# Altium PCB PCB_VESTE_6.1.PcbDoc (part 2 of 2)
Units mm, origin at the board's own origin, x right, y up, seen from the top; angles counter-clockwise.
Board outline 60.48 x 91 mm, 4 copper layers (Top Copper (GND), Signal Layer 1 (PWR), Signal Layer 2 (GND), Bottom Copper(SIG)), stack 0.97 mm thick; 103 components, 68 nets, 385 pads, 720 vias.
Unrouted connection lines stored in the file: 5.
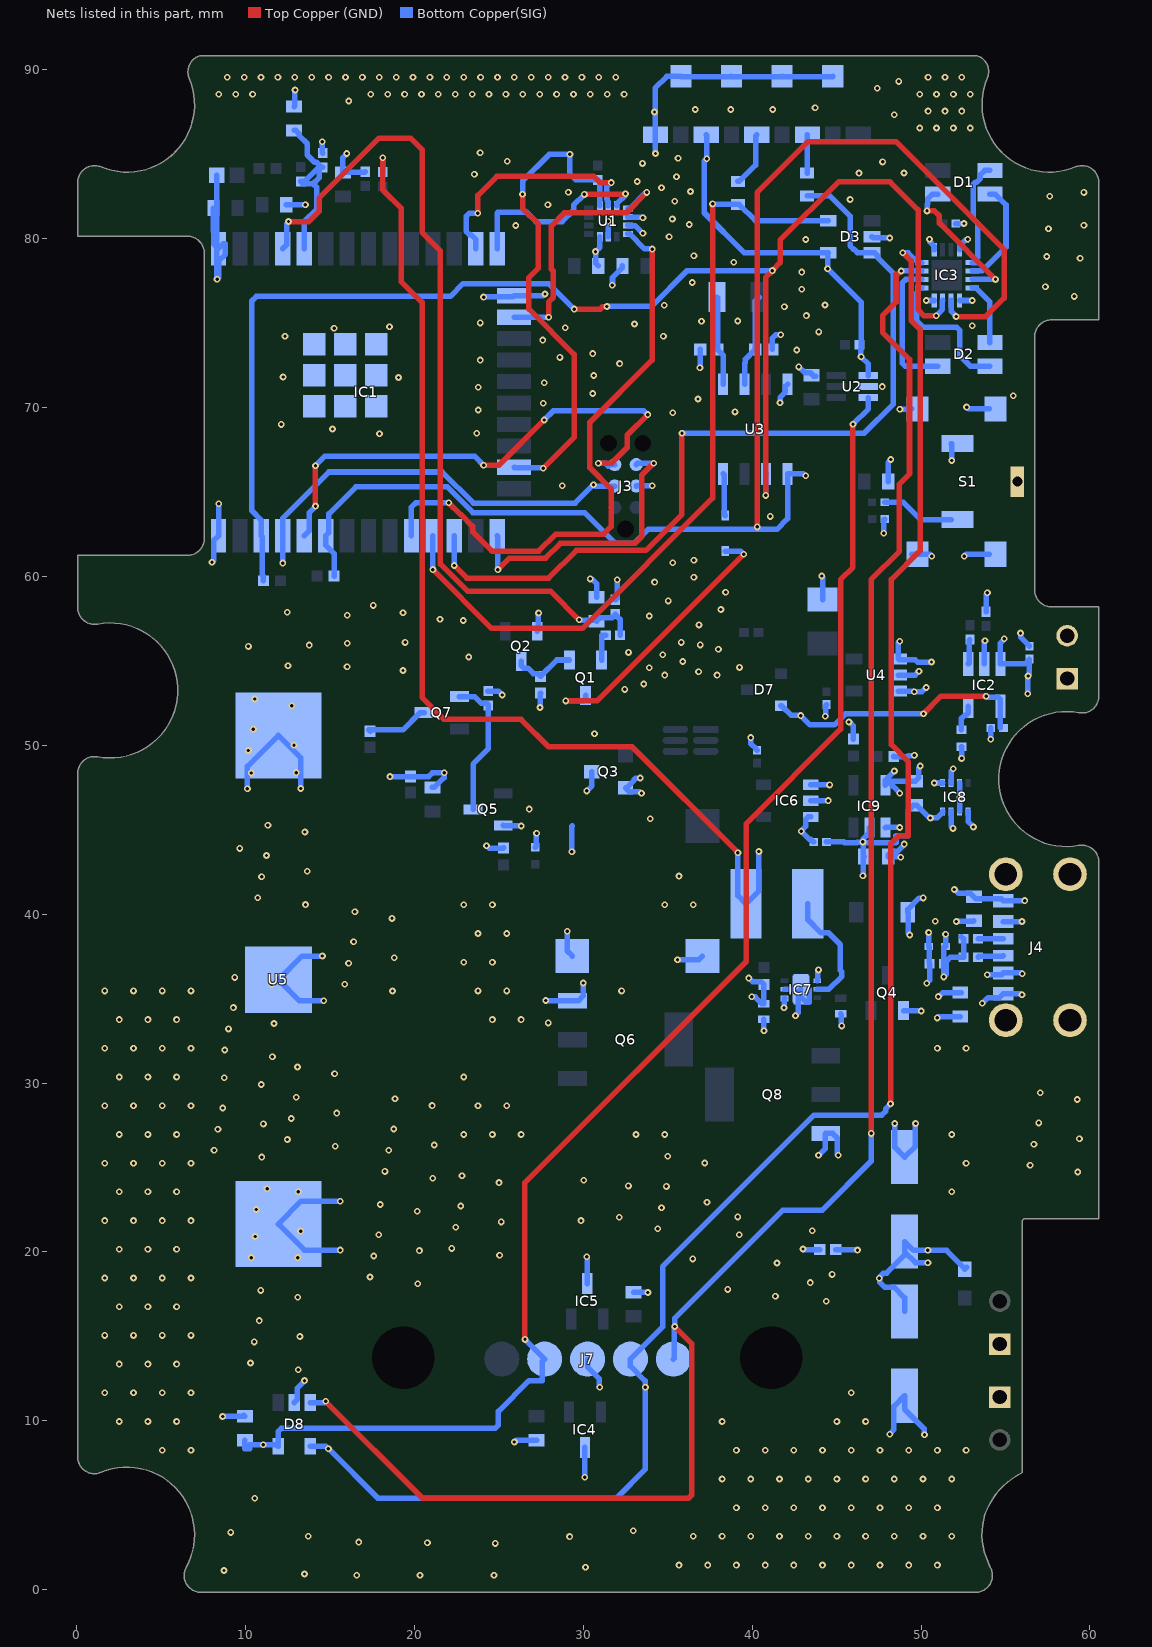
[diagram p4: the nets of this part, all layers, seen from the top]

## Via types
v1: diameter 0.4, hole 0.2, Top Copper (GND) to Bottom Copper(SIG), 720 vias

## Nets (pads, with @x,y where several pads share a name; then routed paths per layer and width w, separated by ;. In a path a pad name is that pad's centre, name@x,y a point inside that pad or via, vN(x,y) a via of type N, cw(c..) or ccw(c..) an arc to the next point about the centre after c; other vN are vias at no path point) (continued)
GND: C1.2 C2.2 C3.2 C4.2 C5.2 C6.2 C7.2 C8.2 C9.2 C10.2 C11.2 C12.2 C13.2 C14.2 C15.1 C16.1 C17.2 C18.2 C19.2 C20.2 C21.2 C22.2 C23.2 C24.2 C25.1 C26.2 C27.2 C28.2 C29.2 C30.2 C31.1 C32.2 D3.2 D8.2 IC1.1 IC1.15 IC1.38 IC1.39 IC1.40 IC1.41 IC1.42 IC1.43 IC1.44 IC1.45 IC1.46 IC1.47 IC2.2 IC3.1 IC3.4 IC3.9 IC3.12 IC4.3 IC5.3 IC6.2 IC7.2 IC7.4 IC7.7 IC7.8 IC7.9 IC8.1 IC8.4 IC8.5 IC9.2 J2.2 J3.4 J4.A12 J4.B12 J4.MH1 J4.MH2 J4.MH3 J4.MH4 J7.3 MP1.1 MP2.1 pad.2@51.444,38.09 pad.9 pad.10 pad.11 pad.12 pad.13 Q2.2 Q3.2 Q5.2 Q6.3 Q8.3 R8.1 R9.2 R14.2 R15.1 R17.1 R19.1 R20.1 R21.1 R22.1 R27.2 R28.1 R29.2 R31.2 S1.MP1 S1.MP2 S1.MP3 S1.MP4 S1.MP5 U1.2 U1.3 U1.6 U1.7 U2.2 U3.4 U4.2 U5.3 | length 159.3
  Bottom Copper(SIG) w0.326: v1(8.008,60.837) 8.008,60.857 8.103,60.952 8.103,62.117 IC1.38@8.39,62.404 8.399,62.413 8.399,64.299 v1(8.408,64.307) ; C2.2@8.098,81.813 8.098,80.432 8.103,80.427 8.103,79.691 IC1.1@8.39,79.404 8.677,79.691 8.808,79.691 8.808,79.074 8.404,78.67 8.404,77.703 8.31,77.61 v1(8.31,77.59) 8.289,77.611 C3.2@8.289,83.762 ; v1(8.638,10.254) 8.64,10.256 9.82,10.256 9.883,10.319 C24.2@9.959,10.259 ; C1.2@12.415,82.004 v1(13.542,82.004) ; C6.2@12.867,87.825 12.916,87.873 12.916,88.786 v1(12.93,88.8) ; D8.2@12.879,11.079 13.061,11.261 13.061,11.936 13.485,12.36 v1(13.485,12.38) ; v1(14.537,85.737) 14.552,85.723 14.552,85.092 R8.1@14.576,85.068 ; v1(14.547,37.519) 13.344,37.519 U5.3@11.941,36.116 13.19,34.866 v1(14.627,34.866) ; v1(15.992,85.043) 15.992,85.023 15.765,84.796 C10.2@15.765,83.919 15.786,83.94 17.059,83.94 R17.1@17.08,83.962 ; v1(18.55,48.144) R27.2@19.766,48.144 20.837,48.144 21.064,48.37 v1(21.765,48.37) 21.751,48.356 21.751,48.086 21.165,47.5 C20.2@21.06,47.5 ; v1(24.092,76.539) 24.106,76.553 25.834,76.553 IC1.15@25.9,76.619 27.603,76.619 27.709,76.724 v1(27.728,76.724) ; v1(24.267,44.051) 24.287,44.051 24.425,43.913 25.267,43.913 R28.1@25.277,43.923 ; Q5.2@25.267,45.252 25.286,45.233 26.309,45.233 v1(26.323,45.219) ; v1(25.916,8.745) 25.936,8.745 26.023,8.832 27.224,8.832 C21.2@27.231,8.839 ; C22.2@27.154,43.949 27.215,44.01 27.215,44.772 v1(27.229,44.786) ; Q2.2@27.273,56.762 27.336,56.824 27.336,57.815 v1(27.35,57.83) ; v1(27.768,34.886) 27.778,34.876 29.343,34.876 Q6.3@29.353,34.866 29.7,34.866 29.987,35.153 v1(29.987,35.924) ; v1(30.079,6.655) 30.086,6.663 30.086,8.416 IC4.3@30.094,8.424 ; v1(30.203,19.707) 30.203,19.687 30.231,19.658 IC5.3@30.231,18.126 ; J7.3@30.25,13.65 30.25,13.175 30.95,12.475 30.95,11.994 v1(30.964,11.98) ; v1(30.414,59.851) 30.428,59.837 30.52,59.837 30.787,59.57 C9.2@30.787,58.766 ; C4.2@30.89,78.39 30.732,78.548 30.732,79.217 v1(30.718,79.231) 30.975,79.489 U1.7@30.975,80.119 ; U1.6@31.475,80.119 v1(31.475,81.031) ; v1(31.712,77.237) 31.726,77.251 31.726,77.696 32.315,78.285 C5.2@32.315,78.39 ; R15.1@31.89,58.614 31.993,58.717 31.993,59.784 v1(32.007,59.798) ; U1.3@32.638,80.781 32.65,80.769 33.057,80.769 33.505,80.321 v1(33.525,80.321) ; U1.2@32.638,81.281 33.456,81.281 33.505,81.233 v1(33.525,81.233) ; C23.2@32.977,17.607 32.984,17.599 33.816,17.599 v1(33.823,17.592) ; J3.4@33.134,65.351 33.138,65.356 34.072,65.356 v1(34.076,65.36) ; v1(33.376,48.064) 33.372,48.06 33.105,48.06 33.02,47.975 33.02,47.945 32.553,47.478 Q3.2@32.503,47.478 32.74,47.241 33.343,47.241 33.422,47.161 v1(33.442,47.161) ; v1(34.21,87.5) 34.21,87.48 34.271,87.419 pad.9@34.271,86.151 ; v1(34.271,85.043) 34.257,85.057 34.257,85.608 34.25,85.614 34.25,88.911 34.95,89.611 pad.13@35.771,89.611 35.771,89.586 pad.12@38.771,89.586 ; v1(36.9,72.361) 36.9,72.381 36.925,72.406 C15.1@36.925,73.44 ; pad.12@38.771,89.611 pad.12@38.771,89.586 ; v1(39.789,36.212) 39.809,36.212 40.022,35.999 40.525,35.999 R29.2@40.687,35.837 C30.2@40.687,34.689 40.575,34.689 40.166,35.098 39.99,35.098 v1(39.976,35.112) ; v1(39.909,50.453) 39.924,50.439 39.924,50.088 40.211,49.8 40.211,49.779 C28.2@40.284,49.705 ; C16.1@41.195,73.44 41.195,74.104 41.392,74.3 41.671,74.3 v1(41.685,74.314) ; v1(41.642,70.276) 41.656,70.29 41.656,70.593 41.953,70.89 41.953,71.24 U3.4@42.09,71.377 ; pad.11@41.771,89.611 pad.11@41.771,89.586 ; IC7.2@41.912,35.555 IC7.8@42.412,35.555 ; IC7.8@42.418,35.555 42.418,35.56 IC7.7@42.728,35.25 ; v1(42.559,33.977) 42.559,33.997 42.728,34.166 IC7.7@42.728,35.25 ; v1(42.749,72.406) 42.769,72.406 43.117,72.059 43.442,72.059 43.644,71.857 C14.2@43.749,71.857 ; IC7.7@42.887,35.555 42.728,35.396 IC7.7@42.728,35.25 ; IC7.9@43.362,35.555 43.362,34.773 43.205,34.773 IC7.7@42.728,35.25 ; IC6.2@43.462,46.711 43.47,46.718 44.494,46.718 v1(44.501,46.725) ; IC7.4@43.862,36.055 43.866,36.093 43.866,36.621 43.924,36.679 v1(43.924,36.699) ; v1(43.926,25.716) 44.312,26.102 44.312,26.967 Q8.3@44.361,27.016 44.761,27.016 45.048,26.729 45.048,25.782 45.095,25.736 v1(45.095,25.716) ; v1(44.119,60.024) 44.119,60.004 44.162,59.961 C25.1@44.162,58.63 ; v1(44.331,51.718) 44.345,51.732 44.345,52.342 C26.2@44.412,52.409 ; C27.2@44.393,44.277 45.41,44.277 45.466,44.221 46.183,44.221 46.225,44.263 46.542,44.263 v1(46.556,44.277) ; pad.10@44.771,89.611 44.771,89.586 pad.11@41.771,89.586 ; C29.2@45.242,34.093 45.283,34.052 45.283,33.395 v1(45.297,33.381) ; v1(45.726,51.376) 45.74,51.362 45.778,51.362 45.989,51.151 R31.2@45.989,50.361 ; v1(46.556,42.266) 46.57,42.28 46.57,43.351 C31.1@46.629,43.41 46.584,43.455 46.584,44.263 46.57,44.277 46.584,44.291 46.584,44.472 46.939,44.827 IC9.2@46.939,45.127 ; v1@46.584,44.221 48.514,44.221 48.514,44.628 48.87,44.628 48.895,44.653 49.251,44.653 49.251,46.149 49.545,46.444 49.756,46.444 50.496,45.704 50.535,45.704 v1(50.549,45.69) 50.564,45.704 50.954,45.704 51.278,46.028 IC8.4@51.278,46.089 ; D3.2@47.092,80.119 47.169,80.042 v1(48.146,80.042) ; v1(47.789,62.548) 47.803,62.562 47.803,63.34 R19.1@47.859,63.397 ; C11.2@48.05,65.614 48.05,66.744 48.207,66.901 v1(48.207,66.921) ; v1(48.146,9.203) 48.146,9.223 48.392,9.469 48.392,10.845 C18.2@49.029,11.482 49.029,10.682 50.186,9.524 50.186,9.188 v1(50.2,9.174) ; v1(48.439,27.6) 48.439,26.203 C19.2@49.029,25.614 49.666,26.251 49.666,27.59 v1(49.676,27.6) ; U4.2@48.655,54.156 49.644,54.156 49.871,54.383 v1(49.879,54.383) ; v1(48.745,69.902) 49.426,69.902 S1.MP2@49.439,69.914 ; S1.MP3@49.439,61.314 50.513,61.314 v1(50.629,61.198) ; v1(50.308,76.337) IC3.12@50.777,76.337 ; v1(50.499,79.962) 50.513,79.948 50.513,79.826 50.777,79.561 IC3.1@50.777,79.337 ; v1(50.777,47.765) IC8.5@51.278,47.765 ; v1(50.952,33.855) 50.972,33.855 51.052,33.935 C17.2@52.317,33.935 ; v1(51.337,36.283) v1@51.345,36.291 ; v1(51.453,38.815) 51.448,38.811 51.448,38.094 pad.2@51.444,38.09 51.399,38.09 51.352,38.043 R22.1@51.352,37.069 51.345,37.061 v1@51.345,36.291 ; v1(51.972,41.456) 51.992,41.456 52.223,41.225 52.921,41.225 C13.2@53.123,41.023 53.24,40.906 54.751,40.906 J4.B12@54.867,40.79 56.125,40.79 v1(56.139,40.803) ; C12.2@52.058,80.894 v1(52.537,80.894) ; IC3.9@52.277,76.337 v1(53.027,76.337) ; IC3.4@52.277,79.337 52.277,79.561 52.664,79.948 52.75,79.948 v1(52.764,79.962) ; R20.1@52.383,38.652 52.495,38.54 R20.1@52.52,38.54 R21.1@52.52,37.452 51.736,37.452 51.489,37.206 51.489,36.436 v1@51.345,36.291 ; R14.2@52.39,49.911 52.393,49.908 52.393,49.226 v1(52.397,49.223) ; v1(52.551,61.198) 52.667,61.314 S1.MP4@54.039,61.314 ; v1(52.695,70.027) 52.808,69.914 S1.MP1@54.039,69.914 ; IC8.1@52.777,46.089 52.791,46.076 52.791,45.484 53.096,45.178 v1(53.096,45.158) ; v1(53.621,34.727) 53.641,34.727 53.968,35.053 54.63,35.053 J4.A12@54.867,35.29 55.899,35.29 55.958,35.232 v1(55.978,35.232) ; IC2.2@53.743,54.813 53.743,56.13 53.787,56.174 v1(53.787,56.194) ; R9.2@53.845,57.905 53.845,58.93 53.925,59.01 v1(53.925,59.03) ; C7.2@54.121,51.036 54.121,50.784 54.113,50.792 54.113,50.375 v1(54.127,50.361) ; v1(55.885,56.644) 55.899,56.63 55.899,56.403 56.417,55.886 C8.2@56.417,55.864 ; pad.12@38.771,89.586 pad.11@41.771,89.586
  other v1: 16.587,0.849 20.327,0.849 24.708,0.849 13.485,0.929 8.717,1.13 30.126,1.319 35.664,1.454 37.364,1.454 39.064,1.454 40.764,1.454 42.464,1.454 44.164,1.454 45.864,1.454 47.564,1.454 49.264,1.454 50.964,1.454 24.779,2.735 20.767,2.771 16.694,2.815 13.711,3.154 29.186,3.14 36.514,3.154 38.214,3.154 39.914,3.154 41.614,3.154 43.314,3.154 45.014,3.154 46.714,3.154 48.414,3.154 50.114,3.154 51.814,3.154 9.117,3.387 32.953,3.493 39.064,4.854 40.764,4.854 42.464,4.854 44.164,4.854 45.864,4.854 47.564,4.854 49.264,4.854 50.964,4.854 10.539,5.41 38.214,6.554 39.914,6.554 41.614,6.554 43.314,6.554 45.014,6.554 46.714,6.554 48.414,6.554 50.114,6.554 51.814,6.554 5.064,8.254 6.764,8.254 39.064,8.254 40.764,8.254 42.464,8.254 44.164,8.254 45.864,8.254 47.564,8.254 49.264,8.254 50.964,8.254 52.664,8.254 2.514,9.954 4.214,9.954 5.914,9.954 38.214,9.954 45.014,9.954 46.714,9.954 1.664,11.654 3.364,11.654 5.064,11.654 6.764,11.654 45.864,11.654 13.119,13.023 2.514,13.354 4.214,13.354 5.914,13.354 10.291,13.423 10.517,14.67 13.214,14.99 1.664,15.054 3.364,15.054 5.064,15.054 6.764,15.054 10.811,15.931 2.514,16.754 4.214,16.754 5.914,16.754 44.39,17.07 13.083,17.319 41.372,17.376 10.89,17.719 38.544,17.776 20.197,18.111 43.439,18.182 1.664,18.454 3.364,18.454 5.064,18.454 6.764,18.454 17.369,18.511 44.729,18.666 41.467,19.343 36.478,19.583 17.595,19.757 25.041,19.808 20.292,20.077 2.514,20.154 4.214,20.154 5.914,20.154 22.213,20.208 17.889,21.018 39.233,21.018 43.557,21.245 34.4,21.37 22.439,21.454 25.136,21.775 1.664,21.854 3.364,21.854 5.064,21.854 6.764,21.854 29.864,21.854 32.126,22.054 39.144,22.073 20.162,22.407 34.626,22.616 22.733,22.715 17.969,22.807 37.323,22.937 2.514,23.554 4.214,23.554 5.914,23.554 51.814,23.554 34.92,23.877 32.668,23.906 25.006,24.104 30.028,24.246 21.077,24.366 22.812,24.504 59.281,24.729 18.249,24.766 56.453,25.129 1.664,25.254 3.364,25.254 5.064,25.254 6.764,25.254 52.664,25.254 37.192,25.266 10.96,25.612 34.999,25.666 8.132,26.012 18.475,26.012 15.304,26.253 21.172,26.333 56.679,26.375 12.476,26.653 59.376,26.696 2.514,26.954 4.214,26.954 5.914,26.954 22.914,26.954 24.614,26.954 26.314,26.954 33.114,26.954 34.814,26.954 51.814,26.954 8.358,27.259 18.768,27.273 11.055,27.579 56.972,27.636 12.702,27.899 15.399,28.22 8.652,28.52 1.664,28.654 3.364,28.654 5.064,28.654 6.764,28.654 21.041,28.662 23.764,28.654 25.464,28.654 59.245,29.025 18.848,29.062 12.996,29.16 57.052,29.425 10.925,29.908 8.732,30.308 2.514,30.354 4.214,30.354 5.914,30.354 22.914,30.354 15.269,30.549 13.075,30.949 11.587,31.558 8.759,31.958 1.664,32.054 3.364,32.054 5.064,32.054 6.764,32.054 50.964,32.054 52.664,32.054 8.985,33.205 11.682,33.525 27.919,33.561 2.514,33.754 4.214,33.754 5.914,33.754 24.614,33.754 26.314,33.754 9.279,34.466 1.664,35.454 3.364,35.454 5.064,35.454 6.764,35.454 18.701,35.451 23.764,35.454 25.464,35.454 32.264,35.454 15.873,35.851 11.552,35.855 9.358,36.255 16.099,37.098 22.914,37.154 24.614,37.154 18.796,37.418 16.393,38.359 23.764,38.854 25.464,38.854 50.842,39.576 18.666,39.748 16.473,40.148 13.548,40.566 22.914,40.554 24.614,40.554 34.814,40.554 36.514,40.554 10.72,40.966 10.946,42.213 35.664,42.254 13.643,42.533 11.24,43.474 9.66,43.891 13.513,44.862 11.32,45.262 33.964,45.654 26.791,46.219 30.662,50.689 32.447,53.308 33.582,53.63 34.814,54.154 37.92,54.156 36.822,54.352 19.319,54.43 33.902,54.588 39.248,54.611 16.01,54.649 12.514,54.712 35.892,54.962 23.215,55.23 34.708,55.362 32.676,55.499 37.996,55.681 10.164,55.854 13.767,55.93 36.925,55.942 16.018,56.039 19.446,56.09 35.804,56.09 36.846,57.128 22.885,57.386 21.509,57.465 33.902,57.656 16.018,57.703 19.319,57.849 12.46,57.882 38.147,58.042 17.56,58.282 35.024,58.549 38.423,59.054 34.218,59.664 36.547,59.947 35.298,60.804 36.547,60.949 41.062,63.551 28.745,65.36 17.927,68.447 23.694,68.478 15.145,68.727 12.114,68.999 35.29,69.685 38.983,69.741 23.773,69.85 27.629,70.25 36.79,70.502 55.453,70.702 30.551,70.827 23.773,71.201 47.698,71.24 27.689,71.467 19.051,71.774 12.219,71.804 30.623,71.895 32.146,72.602 23.892,72.809 28.614,72.966 30.551,73.193 42.632,73.404 27.592,73.993 12.335,74.226 34.74,74.226 43.941,74.477 15.24,74.697 28.932,74.724 18.519,74.777 53.027,74.843 33.025,74.949 23.892,75.01 36.998,75.103 39.148,75.12 43.207,75.442 41.904,75.974 34.793,76.053 44.309,76.072 59.076,76.579 42.936,76.998 57.362,77.157 36.447,77.401 42.936,78.02 38.904,78.597 59.415,78.837 57.439,78.942 36.547,78.983 43.165,79.948 35.079,80.119 57.542,80.587 26.003,80.781 59.642,80.798 36.265,80.837 35.275,81.163 27.9,82.004 35.415,82.209 45.797,82.318 57.622,82.511 59.642,82.738 29.115,82.752 36.344,82.794 34.628,83.02 33.199,83.385 35.517,83.659 23.55,83.815 46.32,83.883 48.985,83.886 33.504,84.457 47.72,84.545 25.494,84.58 35.611,84.763 23.886,85.088 49.915,86.554 50.915,86.554 51.915,86.554 52.915,86.554 48.411,87.34 50.415,87.554 51.415,87.554 52.415,87.554 36.632,87.646 38.727,87.646 41.21,87.646 43.724,87.758 16.114,88.154 8.414,88.554 9.414,88.554 10.414,88.554 17.414,88.554 18.414,88.554 19.415,88.554 20.415,88.554 21.415,88.554 22.415,88.554 23.415,88.554 24.415,88.554 25.415,88.554 26.415,88.554 27.415,88.554 28.415,88.554 29.415,88.554 30.415,88.554 31.415,88.554 32.415,88.554 49.915,88.554 50.915,88.554 51.915,88.554 52.915,88.554 47.407,88.913 48.678,89.313 8.914,89.554 9.914,89.554 10.914,89.554 11.914,89.554 12.914,89.554 13.914,89.554 14.914,89.554 15.914,89.554 16.914,89.554 17.914,89.554 18.914,89.554 19.914,89.554 20.914,89.554 21.915,89.554 22.915,89.554 23.915,89.554 24.915,89.554 25.915,89.554 26.915,89.554 27.915,89.554 28.915,89.554 29.915,89.554 30.915,89.554 31.915,89.554 50.415,89.554 51.415,89.554 52.415,89.554
ILED1: D1.3 IC3.5 | length 6.5
  Bottom Copper(SIG) w0.326: IC3.5@53.027,78.587 53.251,78.587 53.264,78.6 53.264,78.824 53.346,78.906 53.346,80.916 53.076,81.187 53.076,83.197 53.223,83.345 53.299,83.345 53.491,83.536 53.491,83.756 53.778,84.043 D1.3@54.078,84.043
ILED2: D1.4 IC3.6 | length 6.3
  Bottom Copper(SIG) w0.326: IC3.6@53.027,78.087 53.041,78.1 53.628,78.1 55.027,79.5 55.027,81.993 54.378,82.643 D1.4@54.078,82.643
ILED3: D1.2 IC3.7 | length 8.8
  Top Copper (GND) w0.326: v1(50.348,81.643) 50.793,81.643 51.079,81.356 51.079,80.914 v1(54.406,77.587)
  Bottom Copper(SIG) w0.326: v1(50.348,81.643) 50.362,81.657 50.362,82.028 50.391,82.056 50.391,82.356 50.678,82.643 D1.2@50.977,82.643 ; IC3.7@53.027,77.587 v1(54.406,77.587)
ILED4: D2.3 IC3.8 | length 3.8
  Bottom Copper(SIG) w0.326: IC3.8@53.027,77.087 53.251,77.087 54.078,76.261 D2.3@54.078,73.843
ILED5: D2.4 IC3.13 | length 8.5
  Bottom Copper(SIG) w0.326: IC3.13@50.027,77.087 49.804,77.087 49.79,77.074 49.79,76.85 49.75,76.81 49.75,75.12 50.11,74.761 52.105,74.761 52.296,74.57 52.296,73.065 52.918,72.443 D2.4@54.078,72.443
ILED6: D2.2 IC3.14 | length 8.2
  Bottom Copper(SIG) w0.326: IC3.14@50.027,77.587 49.091,77.587 48.883,77.379 48.883,72.634 49.074,72.443 D2.2@50.977,72.443
INT1: IC1.29 U1.4 | length 35.9
  Top Copper (GND) w0.326: v1(22.029,64.358) 22.732,63.655 22.756,63.655 23.445,62.966 23.445,62.645 24.597,61.494 27.355,61.494 28.371,62.51 31.204,62.51 31.648,62.954 31.648,65.176 30.378,66.446 30.378,69.113 34.076,72.811 v1(34.076,79.383)
  Bottom Copper(SIG) w0.326: IC1.29@19.82,62.404 19.82,64.102 20.076,64.358 v1(22.029,64.358) ; U1.4@32.638,80.281 32.75,80.281 33.635,79.397 34.062,79.397 v1(34.076,79.383)
IO0: IC1.25 J3.6 | length 17
  Top Copper (GND) w0.326: v1(24.941,60.404) 25.615,61.079 27.77,61.079 28.642,61.951 33.058,61.951 33.458,62.351 33.458,65.993 v1(34.165,66.7)
  Bottom Copper(SIG) w0.326: IC1.25@24.9,62.404 24.927,62.378 24.927,60.418 v1(24.941,60.404) ; J3.6@33.134,66.621 33.199,66.686 34.151,66.686 v1(34.165,66.7)
LED_SANGLE_G: D8.3 IC3.15 J7.5 | length 109.4
  Top Copper (GND) w0.326: v1(14.739,11.149) 20.478,5.41 36.222,5.41 36.414,5.601 36.414,14.574 v1(35.41,15.578) ; v1(47.046,27.016) 47.046,59.808 48.717,61.479 48.717,65.468 49.313,66.064 49.313,72.851 47.72,74.444 47.72,75.442 48.514,76.236 48.514,77.88 48.607,77.88 48.811,78.083 v1(48.831,78.083)
  Bottom Copper(SIG) w0.326: D8.3@13.829,11.079 14.649,11.079 14.719,11.149 v1(14.739,11.149) ; J7.5@35.33,13.65 35.395,13.715 35.395,15.564 v1(35.41,15.578) 35.41,16.064 41.799,22.453 44.133,22.453 47.046,25.366 v1(47.046,27.016) ; v1(48.831,78.083) 48.833,78.085 50.025,78.085 IC3.15@50.027,78.087
LED_SANGLE_R: D8.4 IC3.16 J7.4 | length 106.6
  Top Copper (GND) w0.326: v1(48.19,28.775) 48.19,44.162 48.666,44.638 49.251,44.638 49.251,49.022 48.235,50.038 48.235,59.817 49.936,61.519 49.936,74.625 49.403,75.158 49.403,78.679 v1(48.913,79.169)
  Bottom Copper(SIG) w0.326: D8.4@13.829,8.489 14.739,8.489 14.884,8.345 v1(14.904,8.345) 17.838,5.41 31.953,5.41 33.676,7.133 v1(33.676,11.98) 33.662,11.994 33.662,12.359 32.79,13.231 J7.4@32.79,13.65 34.696,15.556 34.696,19.126 43.663,28.092 47.667,28.092 47.898,28.323 47.898,28.463 48.19,28.755 v1(48.19,28.775) ; v1(48.913,79.169) 48.927,79.155 49.236,79.155 49.804,78.587 IC3.16@50.027,78.587
LX: IC7.5 L1.2 | length 7.2
  Bottom Copper(SIG) w0.326: L1.2@43.287,40.613 43.287,39.672 44.049,38.91 44.501,38.91 45.223,38.188 45.223,36.665 45.304,36.584 45.304,36.314 44.545,35.555 IC7.5@43.862,35.555
MOS_GND: pad.3@29.349,37.519 pad.4@29.349,45.219 pad.- Q3.3 | length 6
  Bottom Copper(SIG) w0.326: v1(29.047,38.99) 29.047,37.822 pad.3@29.349,37.519 ; v1(29.322,43.698) 29.322,45.192 pad.4@29.349,45.219 ; v1(30.203,47.299) 30.503,47.599 Q3.3@30.503,48.428 ; v1(35.574,37.293) 36.822,37.293 pad.-@37.049,37.519
N_DETECT_SELLE: D3.4 pad.7 R11.2 U2.1 | length 21.3
  Bottom Copper(SIG) w0.326: pad.7@37.271,86.151 37.3,86.122 v1(37.3,84.724) 37.16,84.584 37.16,81.534 39.525,79.169 D3.4@44.502,79.169 44.464,79.131 v1(44.464,78.221) 46.45,76.235 46.45,73.464 46.434,73.447 46.434,73.028 v1(46.448,73.014) 46.448,73.004 46.873,72.579 U2.1@46.873,71.89
N_HALL2: C24.1 D8.5 J7.2 U2.3 | length 88.1
  Top Copper (GND) w0.326: v1(26.542,14.818) 26.542,24.104 39.649,37.211 39.649,45.364 45.236,50.951 45.236,59.805 45.967,60.536 v1(45.967,69.012)
  Bottom Copper(SIG) w0.326: C24.1@9.959,8.839 9.957,8.839 9.957,8.355 10.236,8.355 10.236,8.574 v1(11.04,8.574) 11.844,8.574 D8.5@11.929,8.489 11.929,9.358 12.12,9.549 24.779,9.549 24.97,9.74 24.97,10.559 26.791,12.38 27.577,12.38 27.577,13.517 J7.2@27.71,13.65 v1(26.542,14.818) ; v1(45.967,69.012) 46.873,69.918 U2.3@46.873,70.59
NetD6_2: D6.2 U3.8 | length 2.5
  Bottom Copper(SIG) w0.326: U3.8@38.28,66.077 38.342,66.015 38.342,63.663 D6.2@38.404,63.602
NetJ1_3: pad.3@43.271,86.151 R10.2 | length 2.3
  Bottom Copper(SIG) w0.326: R10.2@43.249,83.886 43.249,86.129 pad.3@43.271,86.151
NetJ1_5: pad.5 R13.2 | length 3.3
  Bottom Copper(SIG) w0.326: R13.2@39.154,83.385 39.23,83.385 40.205,84.36 40.205,86.085 pad.5@40.271,86.151
NetJ4_A5: J4.A5 R20.2 | length 1.5
  Bottom Copper(SIG) w0.326: R20.2@53.37,38.54 J4.A5@54.867,38.54
NetJ4_B5: J4.B5 R21.2 | length 1.5
  Bottom Copper(SIG) w0.326: R21.2@53.37,37.452 53.414,37.496 54.824,37.496 J4.B5@54.867,37.54
NetQ1_1: Q1.1 Q2.3 R4.2 | length 3.8
  Bottom Copper(SIG) w0.326: Q2.3@26.323,54.962 26.323,54.712 26.46,54.575 26.71,54.575 27.037,54.247 27.308,54.247 R4.2@27.47,54.086 28.433,55.049 Q1.1@29.168,55.049
NetQ1_2: Q1.2 R7.2 | length 1.7
  Bottom Copper(SIG) w0.326: Q1.2@31.088,55.049 31.088,56.377 31.088,56.514 R7.2@31.326,56.514
NetQ5_3: Q5.3 Q7.1 R25.1 | length 8.5
  Bottom Copper(SIG) w0.326: Q7.1@22.665,52.886 23.564,52.886 23.951,52.5 24.255,52.5 24.367,52.388 R25.1@24.367,52.363 24.367,49.788 23.467,48.888 Q5.3@23.467,46.202
NetQ7_3: Q7.3 R26.1 | length 3.8
  Bottom Copper(SIG) w0.326: R26.1@17.377,50.829 17.28,50.905 19.319,50.905 20.34,51.926 Q7.3@20.565,51.926
NetR18_1: R18.1 S1.2 | length 4.4
  Bottom Copper(SIG) w0.326: R18.1@47.844,64.397 48.931,64.397 49.964,63.364 S1.2@51.789,63.364
OSCI: C15.2 U3.1 Y1.2 | length 5.3
  Bottom Copper(SIG) w0.326: Y1.2@37.904,76.542 37.945,76.501 C15.2@37.945,73.44 38.28,73.105 U3.1@38.28,71.377
OSCO: C16.2 U3.2 | length 5.5
  Bottom Copper(SIG) w0.326: U3.2@39.55,71.377 39.55,72.607 39.586,72.643 39.586,72.851 C16.2@40.175,73.44 40.175,76.314 40.404,76.542
PILE_LVL: C9.1 IC1.4 R7.1 R15.2 | length 50.7
  Top Copper (GND) w0.326: v1(12.54,81.013) 13.754,81.013 14.351,81.61 14.351,82.398 17.907,85.954 19.761,85.954 20.447,85.268 20.447,80.366 21.539,79.273 21.539,60.731 23.165,59.106 28.076,59.106 v1(29.753,57.43)
  Bottom Copper(SIG) w0.326: IC1.4@12.2,79.404 12.44,79.645 12.44,80.893 12.54,80.993 v1(12.54,81.013) ; v1(29.753,57.43) 29.767,57.415 30.718,57.415 C9.1@30.787,57.346 30.989,57.548 31.699,57.548 R15.2@31.89,57.739 ; R15.2@31.89,57.764 R15.2@31.89,57.739 ; R7.1@32.176,56.514 32.176,57.454 R15.2@31.89,57.739
PROG: IC2.5 R14.1 | length 1.6
  Bottom Copper(SIG) w0.326: R14.1@52.39,50.911 52.39,51.585 52.581,51.776 52.656,51.776 52.793,51.913 IC2.5@52.793,52.313
REF_V165: C6.1 IC1.5 R6.1 R8.2 | length 10.8
  Bottom Copper(SIG) w0.326: C6.1@12.867,86.405 12.972,86.405 13.174,86.203 13.174,86.098 13.651,85.621 13.651,84.96 14.086,84.525 14.192,84.525 14.465,84.252 14.465,84.227 14.353,84.115 14.353,83.597 14.006,83.25 ; IC1.5@13.47,79.404 13.47,81.002 14.215,81.747 14.215,83.04 14.006,83.25 ; R8.2@14.576,84.218 14.319,84.218 13.487,83.387 R6.1@13.267,83.387 13.267,83.362 13.379,83.25 14.006,83.25
RXD0: IC1.34 J3.5 | length 31.7
  Top Copper (GND) w0.326: v1(14.137,64.161) v1(14.137,66.555) ; v1(24.094,66.581) 24.998,66.581 v1(27.678,69.261) ; v1(30.89,66.7) 31.674,66.7 32.601,67.627 32.601,68.364 v1(33.818,69.582)
  Bottom Copper(SIG) w0.326: IC1.34@13.47,62.404 13.757,62.691 13.757,63.761 14.137,64.141 v1(14.137,64.161) ; v1(14.137,66.555) 14.683,67.1 23.575,67.1 v1(24.094,66.581) ; v1(27.678,69.261) 28.225,69.808 33.572,69.808 33.798,69.582 v1(33.818,69.582) ; v1(30.89,66.7) 30.904,66.686 31.317,66.686 31.483,66.521 31.483,66.621 J3.5@31.864,66.621
RXD1: D3.3 IC1.27 R10.1 | length 51
  Top Copper (GND) w0.326: v1(22.36,60.643) 23.11,59.893 27.94,59.893 29.582,61.536 33.706,61.536 35.839,63.669 v1(35.839,68.478)
  Bottom Copper(SIG) w0.326: v1(22.36,60.643) IC1.27@22.36,62.404 ; v1(35.839,68.478) 46.634,68.478 48.361,70.205 48.361,77.944 47.424,78.881 47.424,78.987 47.242,79.169 D3.3@47.138,79.169 ; R10.1@43.249,82.532 44.235,82.532 44.602,82.532 45.797,81.338 45.797,79.574 45.988,79.383 46.02,79.383 46.234,79.169 D3.3@47.092,79.169
SCL: IC1.36 IC3.11 R3.2 U3.6 | length 84.9
  Top Copper (GND) w0.326: v1(29.454,75.829) 31.005,75.829 31.146,75.97 31.382,75.97 v1(31.396,75.984) ; v1(40.795,64.797) 40.795,77.687 41.195,78.087 v1(41.195,78.107) 41.195,78.127 41.655,78.588 41.655,79.908 45.11,83.363 48.158,83.363 49.818,81.703 49.818,75.794 50.183,75.429 v1(50.899,75.429)
  Bottom Copper(SIG) w0.326: R3.2@11.057,59.743 11.057,60.018 10.994,60.081 10.994,62.341 IC1.36@10.93,62.404 10.93,63.322 10.363,63.889 10.363,76.302 10.643,76.581 22.123,76.581 22.885,77.343 27.94,77.343 v1(29.454,75.829) ; v1(31.396,75.984) 34.031,75.984 36.154,78.107 v1(41.195,78.107) ; v1(40.795,64.797) 40.808,64.809 40.808,66.064 U3.6@40.82,66.077 ; v1(50.899,75.429) 50.899,75.449 51.264,75.815 51.264,76.324 IC3.11@51.277,76.337
SDA: IC1.33 IC3.10 R2.2 U3.5 | length 83.1
  Top Copper (GND) w0.326: v1@40.284,62.948 40.284,82.728 43.307,85.75 48.514,85.75 54.915,79.35 54.915,76.479 53.824,75.389 v1(52.072,75.389)
  Bottom Copper(SIG) w0.326: R2.2@15.24,60.018 15.24,61.354 14.74,61.854 IC1.33@14.74,62.404 14.932,62.596 14.932,63.702 16.524,65.294 21.942,65.294 23.457,63.779 30.075,63.779 31.902,61.952 32.996,61.952 33.833,62.789 41.455,62.789 42.09,63.424 U3.5@42.09,66.077 43.021,66.077 43.142,65.955 v1(43.162,65.955) ; IC3.10@51.777,76.337 51.791,76.324 51.791,75.691 52.072,75.409 v1(52.072,75.389)
  other v1: 40.302,62.93
SPI_CLK: IC1.13 U1.13 | length 14.1
  Top Copper (GND) w0.326: v1(23.753,81.511) 23.753,82.567 24.876,83.69 30.625,83.69 30.995,83.32 v1(31.649,83.32)
  Bottom Copper(SIG) w0.326: IC1.13@23.63,79.404 23.63,79.954 23.343,80.241 23.253,80.241 23.062,80.432 23.062,81.314 23.259,81.511 v1(23.753,81.511) ; U1.13@31.475,81.944 31.463,81.956 31.463,82.188 31.402,82.249 31.402,82.336 31.378,82.36 31.378,83.092 31.592,83.306 31.635,83.306 v1(31.649,83.32)
SPI_CS_LSM6: IC1.23 R5.1 U1.12 | length 29.3
  Top Copper (GND) w0.326: v1(26.4,82.63) 26.4,81.798 27.339,80.859 27.339,78.251 26.776,77.688 26.776,75.82 29.451,73.146 29.451,68.228 v1(27.629,66.407)
  Bottom Copper(SIG) w0.326: IC1.23@25.9,66.459 25.939,66.421 27.615,66.421 v1(27.629,66.407) ; v1(26.4,82.63) 26.4,83.416 27.982,84.997 v1(29.206,84.997) 29.206,83.826 29.555,83.477 R5.1@30.848,83.477 30.96,83.365 30.96,83.152 30.963,83.149 30.963,81.956 U1.12@30.975,81.944
SPI_MISO: IC1.14 U1.14 | length 11.8
  Top Copper (GND) w0.326: v1(30.063,82.62) 32.441,82.62 32.476,82.656 v1(32.496,82.656)
  Bottom Copper(SIG) w0.326: IC1.14@24.9,79.404 24.9,81.503 24.941,81.543 24.941,81.563 26.635,81.563 27.194,81.005 28.748,81.005 29.425,81.682 29.425,81.983 v1(30.063,82.62) ; U1.14@31.975,81.944 31.987,81.956 31.987,82.068 32.482,82.563 32.482,82.642 v1(32.496,82.656)
SPI_MOSI: IC1.16 U1.1 | length 15.6
  Top Copper (GND) w0.326: v1(27.94,75.349) 27.94,76.243 28.219,76.522 28.219,78.071 28.103,78.187 28.103,80.757 28.88,81.534 32.548,81.534 v1(33.752,82.738)
  Bottom Copper(SIG) w0.326: IC1.16@25.9,75.349 v1(27.94,75.349) ; U1.1@32.638,81.781 32.75,81.781 33.693,82.724 33.738,82.724 v1(33.752,82.738)
STATUS: IC2.1 R12.2 | length 1.5
  Bottom Copper(SIG) w0.326: IC2.1@52.793,54.813 52.844,54.864 52.844,56.207 R12.2@52.895,56.258
TXD0: IC1.35 J3.3 | length 24.7
  Bottom Copper(SIG) w0.326: v1(12.193,60.787) 12.197,60.791 12.197,62.401 IC1.35@12.2,62.404 ; IC1.35@12.193,62.401 12.193,63.441 14.934,66.181 21.642,66.181 23.484,64.34 29.512,64.34 v1(30.603,65.43) 30.623,65.43 30.702,65.351 J3.3@31.864,65.351
TXD1: D3.5 IC1.28 R13.1 | length 47.9
  Top Copper (GND) w0.326: v1(21.09,60.404) 24.573,56.921 29.938,56.921 37.654,64.637 v1(37.654,82.056)
  Bottom Copper(SIG) w0.326: v1(21.09,60.404) IC1.28@21.09,62.404 ; v1(37.654,82.056) 37.666,82.044 39.142,82.044 R13.1@39.154,82.032 39.23,82.032 40.194,81.069 D3.5@44.502,81.069
VBAT: C8.1 IC2.3 IC8.6 J2.1 S1.1 U4.1 U4.3 | length 12.3
  Bottom Copper(SIG) w0.326: U4.3@48.655,53.206 49.53,53.206 49.57,53.166 v1(49.59,53.166) 49.604,53.18 50.051,53.18 50.289,53.418 v1(50.308,53.418) ; v1(48.739,56.156) 48.739,56.136 48.66,56.057 48.66,55.111 48.694,55.077 49.644,55.077 49.791,54.93 v1(50.615,54.93) ; IC8.6@51.777,47.765 51.777,48.457 51.903,48.583 v1(51.903,48.603) ; S1.1@51.789,67.864 51.81,67.843 v1(51.81,66.86) ; v1(54.931,56.305) 54.931,56.285 54.699,56.053 54.699,54.818 IC2.3@54.693,54.813 56.144,54.813 56.417,55.086 C8.1@56.417,55.107 56.417,54.201 56.337,54.121 v1(56.337,54.101) 56.327,54.091 56.327,53.065 v1(56.317,53.055)
VPYRO: D6.1 Q1.3 R4.1 R23.2 R25.2 U5.1 U5.2 | length 35.7
  Top Copper (GND) w0.326: v1(28.953,52.627) 30.815,52.627 v1(39.502,61.314)
  Bottom Copper(SIG) w0.326: v1(10.107,47.427) 10.107,48.747 U5.1@11.941,50.581 13.27,49.252 v1(13.27,47.442) ; v1(15.6,20.107) 13.485,20.107 U5.2@11.941,21.651 13.29,23 v1(15.6,23) ; R25.2@24.325,53.213 R25.2@24.367,53.213 24.964,53.213 v1(25.197,52.98) ; v1(27.429,52.238) 27.444,52.252 27.444,53.059 R4.1@27.47,53.086 ; v1(28.953,52.627) 29.966,52.627 30.128,52.789 Q1.3@30.128,52.949 ; D6.1@38.404,61.492 39.304,61.492 39.482,61.314 v1(39.502,61.314) ; v1(43.007,20.171) 43.027,20.171 43.059,20.139 43.945,20.139 R23.2@43.995,20.139
  other v1: 10.335,19.663 13.083,19.663 10.561,20.909 13.258,21.23 10.628,22.509 13.128,23.559 11.274,23.732 10.341,48.361 12.996,48.38 10.167,49.687 12.864,50.007 10.461,50.948 12.734,52.337 10.541,52.737
VPYRO_COND: C18.1 C19.1 pad.1@54.661,11.405 pad.1@54.662,14.542 R23.1 R24.2 | length 13.2
  Bottom Copper(SIG) w0.326: R23.1@44.945,20.139 46.18,20.139 46.212,20.107 v1(46.232,20.107) ; C18.1@49.029,16.482 49.029,17.282 48.392,17.919 47.837,17.919 47.543,18.212 47.543,18.425 v1(47.529,18.439) 47.543,18.453 47.543,18.509 47.773,18.74 47.954,18.74 49.029,19.814 C19.1@49.029,19.995 ; v1(50.402,19.358) 49.666,19.358 C19.1@49.029,19.995 ; R24.2@52.713,19.1 R24.2@52.582,18.969 52.582,19.019 51.51,20.091 v1(50.402,20.091) 49.551,20.091 C19.1@49.029,20.614 C19.1@49.029,19.995
VSOURCE: C32.1 IC8.2 IC8.7 IC9.5 R32.2 | length 7.7
  Bottom Copper(SIG) w0.326: IC9.5@47.889,47.627 47.889,47.927 48.405,48.443 48.405,48.463 v1(48.419,48.477) ; R32.2@48.381,49.336 48.386,49.332 49.195,49.332 49.256,49.392 49.588,49.392 v1(49.602,49.406) ; v1(48.739,47.161) 48.03,47.87 C32.1@49.539,47.87 ; C32.1@49.545,47.864 49.65,47.864 49.852,48.066 49.852,48.657 49.945,48.75 v1(49.945,48.77) ; IC8.2@52.278,46.089 52.284,46.095 52.284,46.917 v1(52.29,46.923) 52.284,46.929 52.284,47.759 IC8.7@52.278,47.765
VSWITCH: C27.1 C30.1 C31.2 IC6.1 IC6.3 IC7.1 IC9.1 L1.1 R16.2 | length 70.4
  Top Copper (GND) w0.326: v1(18.122,84.783) 18.122,82.893 19.228,81.788 19.228,77.445 20.447,76.225 20.447,52.832 21.742,51.537 26.314,51.537 27.94,49.911 32.882,49.911 v1(39.154,43.64)
  Bottom Copper(SIG) w0.326: R16.2@18.122,83.948 v1(18.122,84.783) ; v1(39.154,43.64) 39.154,41.097 L1.1@39.637,40.613 40.395,41.37 v1(40.395,43.712) ; C30.1@40.687,33.764 40.693,33.759 40.693,33.098 v1(40.698,33.093) ; v1(41.878,34.457) 41.892,34.471 41.892,34.993 41.904,35.005 IC7.1@41.912,35.005 ; IC6.3@43.462,45.761 43.312,45.761 43.175,45.624 43.175,45.207 42.899,44.931 v1(42.899,44.911) 43.386,44.423 43.468,44.423 43.614,44.277 C27.1@43.636,44.277 ; IC6.1@43.462,47.661 43.466,47.657 44.577,47.657 v1(44.581,47.653) ; IC9.1@47.889,45.127 47.893,45.131 v1(48.739,45.131) ; v1(48.802,43.371) 48.788,43.385 48.074,43.385 C31.2@48.049,43.41 48.049,43.515 48.251,43.717 48.596,43.717 48.985,44.105 48.985,44.134 v1(48.999,44.148)
VUSB: C7.1 C13.1 C17.1 D5.2 D7.2 IC2.4 IC8.3 J4.A9 J4.B9 pad.1@50.444,38.09 Q4.1 R22.2 | length 29.6
  Top Copper (GND) w0.326: v1(50.14,51.867) 51.181,52.908 v1(53.848,52.908)
  Bottom Copper(SIG) w0.326: D7.2@41.699,52.338 41.748,52.338 42.314,51.773 42.857,51.773 v1(42.871,51.758) 43.424,51.206 44.863,51.206 45.523,51.867 v1(50.14,51.867) ; Q4.1@48.966,34.293 49.954,34.293 49.983,34.264 v1(50.002,34.264) ; v1(49.33,38.763) 49.33,38.783 49.237,38.877 49.237,40.094 D5.2@49.217,40.113 49.217,40.288 49.878,40.949 50.106,40.949 v1(50.12,40.963) ; v1(50.341,35.908) 50.341,35.928 50.503,36.089 R22.2@50.503,37.069 50.473,37.099 50.473,38.061 pad.1@50.444,38.09 v1(50.444,38.91) ; v1(51.026,35.116) 51.046,35.116 51.273,35.343 C17.1@52.376,35.343 ; IC8.3@51.777,46.089 51.777,45.211 51.89,45.098 v1(51.89,45.078) ; v1(52.091,39.562) 52.105,39.576 53.096,39.576 C13.1@53.123,39.603 ; v1(53.848,52.908) 53.868,52.908 53.926,52.85 54.556,52.85 54.693,52.713 C7.1@54.693,51.034 ; v1(53.911,36.407) 53.925,36.421 54.768,36.421 J4.A9@54.867,36.52 55.923,36.52 55.97,36.472 v1(55.99,36.472) ; J4.B9@54.867,39.56 54.869,39.561 55.976,39.561 v1(55.978,39.563)
pads on no net: IC1.17 IC1.18 IC1.19 IC1.20 IC1.21 IC1.22 IC1.32 IC3.17 IC6.4 J3.7 J3.8 J3.9 U1.9 U1.10 U1.11 U3.3 U3.7 Y1.1

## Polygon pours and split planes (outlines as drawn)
3V3 on Signal Layer 1 (PWR) "3V3_L02_P014" (solid, remove dead copper, pour order 14): 7.583,56.562 7.553,56.591 7.837,87.5 30.829,87.5 31.8,86.529 31.8,84.743 43.441,84.743 43.441,79.619 49.75,79.619 49.75,85.759 60.53,85.759 60.53,75.192 60.332,75.39 53.345,75.39 53.345,71.895 53.093,71.643 47.484,71.643 47.484,72.955 45.962,74.477 41.919,74.477 41.919,78.221 41.699,78.442 36.499,78.442 35.079,77.022 35.079,62.548 37.002,60.625 42.412,60.625 42.412,48.333 41.919,47.299 41.919,46.584 35.787,46.584 35.787,53.999 35.787,56.562
VUSB on Signal Layer 1 (PWR) "VUSB_L02_P005" (solid, remove dead copper, pour order 5): 60.327,40.282 55.544,40.282 55.544,50.849 55.544,53.205 53.419,53.205 53.419,45.69 51.972,45.69 51.972,46.37 51.517,46.37 51.517,41.357 48.006,41.357 48.006,38.268 48.976,38.268 48.976,32.916 60.327,32.916
3V3_LC on Signal Layer 1 (PWR) "3V3_LC_L02_P008" (solid, remove dead copper, pour order 8): 7.553,-0.22 7.553,17.001 34.6,17.001 34.6,-0.22
VPYRO on Signal Layer 1 (PWR) "VPYRO_L02_P009" (solid, remove dead copper, pour order 9): 7.553,53.285 19.458,53.25 19.496,53.288 30.972,53.288 30.995,51.71 30.027,51.725 29.951,48.928 23.294,48.928 22.131,47.765 22.23,26.156 43.47,26.156 43.47,18.467 7.553,18.467
VPYRO_COND on Signal Layer 1 (PWR) "VPYRO_COND_L02_P011" (solid, remove dead copper, pour order 11): 44.47,23.125 44.47,15.975 50.331,10.114 55.83,10.114 55.83,15.733 51.252,15.733 51.252,23.123 51.25,23.125
ALUM_PYRO on Signal Layer 1 (PWR) "ALUM_PYRO_L02_P012" (solid, remove dead copper, pour order 12): 28.382,28.106 28.417,34.518 38.061,34.518 38.061,31.314 38.25,31.125 60.414,31.125 60.531,31.009 60.53,16.245 53.493,16.245 53.493,27.849 53.237,28.106 34.253,28.106
5V on Signal Layer 1 (PWR) "5V_L02_P010" (solid, remove dead copper, pour order 10): 43.287,32.916 47.817,32.916 47.817,35.193 46.736,35.193 46.203,36.295 43.287,36.295 43.287,35.112 43.287,34.293
MOS_GND on Signal Layer 1 (PWR) "MOS_GND_L02_P007" (solid, remove dead copper, pour order 7): 38.061,39.313 38.061,36.166 37.779,36.449 28.174,36.449 28.174,46.349 28.926,47.101 29.717,47.101 29.717,48.726 30.185,49.194 31.228,49.194 31.228,46.278 32.553,44.952 33.714,44.952 33.714,39.263
VSWITCH on Signal Layer 1 (PWR) "VSWITCH_L02_P003" (solid, remove dead copper, pour order 3): 45.139,48.174 42.673,48.174 42.673,45.307 38.634,45.307 38.634,32.916 42.855,32.916 42.855,37.523 42.887,37.555 41.462,38.98 41.462,42.296 45.539,42.296 49.742,42.296 49.742,45.732 49.545,45.929 49.468,45.852 45.459,45.852 45.459,46.76 45.139,47.442 45.139,47.774
5V_SELLE on Signal Layer 1 (PWR) "5V_SELLE_L02_P016" (solid, remove dead copper, pour order 16): 44.415,90.838 49.402,90.838 49.402,80.781 46.26,80.781 44.415,82.626
VBAT on Signal Layer 1 (PWR) "VBAT_L02_P006" (solid, remove dead copper, pour order 6): 55.943,51.363 55.943,54.011 53.308,54.011 53.308,48.314 51.66,48.321 51.66,52.656 47.882,52.656 47.927,68.227 56.042,68.227 56.042,55.611 56.167,55.486 56.194,55.513 60.288,55.513 60.327,55.475 60.327,51.712
VSOURCE on Signal Layer 1 (PWR) "VSOURCE_L02_P004" (solid, remove dead copper, pour order 4): 47.78,50.744 47.78,48.477 46.939,48.477 46.831,48.369 46.831,46.677 51.878,46.677 52.027,46.527 52.027,45.702 52.527,45.702 52.527,48.152 52.027,48.152 52.027,47.177 51.389,47.177 51.389,50.73 51.402,50.744
5V_SELLE on Signal Layer 1 (PWR) "5V_SELLE_L02_P015" (solid, remove dead copper, pour order 15): 46.92,41.646 47.283,41.283 47.283,37.775 47.606,37.452 48.655,37.452 48.655,35.493 47.34,35.493 47.34,36.226 45.552,38.014 45.552,38.98 45.297,38.98 44.892,39.385 44.892,41.646
GND on Signal Layer 2 (GND) "GND_L03_P001" (solid, remove dead copper, pour order 1): 7.553,92.989 61.341,92.989 60.993,-0.309 0.053,-0.142 0.053,38.038 7.553,38.038
GND on Top Copper (GND) "GND_L01_P019" (solid, pour order 19): 0.053,7.862 ccw(c1.053,7.862) 1.438,6.939 cw(c2.977,3.247) 6.482,1.319 ccw(c7.358,0.837) 7.358,-0.162 53.225,-0.162 ccw(c53.225,0.838) 54.102,1.319 cw(c58.745,3.625) 53.616,2.872 cw(c58.647,3.184) 53.767,4.447 cw(c58.841,2.431) 54.642,5.92 cw(c58.524,2.168) 55.996,6.939 55.993,9.925 55.993,14.87 cw(c55.995,14.866) 55.996,14.87 55.996,21.804 cw(c56.16,21.804) 56.159,21.968 60.53,21.968 60.53,43.083 ccw(c59.531,43.083) 59.346,44.066 cw(c58.607,47.997) 59.346,51.928 ccw(c59.53,52.911) 60.53,52.911 60.53,58.192 57.73,58.192 cw(c57.73,59.192) 56.73,59.192 56.73,74.192 cw(c57.73,74.192) 57.73,75.192 60.53,75.192 60.53,83.322 ccw(c59.531,83.322) 59.146,84.245 cw(c57.607,87.937) 53.923,89.496 ccw(c53.002,89.885) 53.308,90.838 7.3,90.838 ccw(c7.584,89.879) 6.663,89.49 cw(c2.977,87.936) 1.438,84.245 ccw(c1.053,83.322) 0.053,83.322 0.053,80.142 6.553,80.142 cw(c6.553,79.142) 7.553,79.142 7.553,62.242 cw(c6.554,62.241) 6.553,61.242 0.053,61.242 0.053,58.161 ccw(c1.053,58.161) 1.238,57.178 cw(c1.977,53.247) 1.238,49.316 ccw(c1.053,48.333) 0.053,48.333
GND on Bottom Copper(SIG) "GND_L04_P020" (solid, pour order 20): 0.053,7.862 ccw(c1.053,7.862) 1.438,6.939 cw(c2.977,3.247) 6.482,1.319 ccw(c7.358,0.837) 7.358,-0.162 53.225,-0.162 ccw(c53.225,0.838) 54.102,1.319 cw(c58.745,3.625) 53.616,2.872 cw(c58.647,3.184) 53.767,4.447 cw(c58.841,2.431) 54.642,5.92 cw(c58.524,2.168) 55.996,6.939 55.993,9.925 55.993,14.87 cw(c55.995,14.866) 55.996,14.87 55.996,21.804 cw(c56.16,21.804) 56.159,21.968 60.53,21.968 60.53,43.083 ccw(c59.531,43.083) 59.346,44.066 cw(c58.607,47.997) 59.346,51.928 ccw(c59.53,52.911) 60.53,52.911 60.53,58.192 57.73,58.192 cw(c57.73,59.192) 56.73,59.192 56.73,74.192 cw(c57.73,74.192) 57.73,75.192 60.53,75.192 60.53,83.322 ccw(c59.531,83.322) 59.146,84.245 cw(c57.607,87.937) 53.923,89.496 ccw(c53.002,89.885) 53.308,90.838 7.3,90.838 ccw(c7.584,89.879) 6.663,89.49 cw(c2.977,87.936) 1.438,84.245 ccw(c1.053,83.322) 0.053,83.322 0.053,80.142 6.553,80.142 cw(c6.553,79.142) 7.553,79.142 7.553,62.242 cw(c6.554,62.241) 6.553,61.242 0.053,61.242 0.053,58.161 ccw(c1.053,58.161) 1.238,57.178 cw(c1.977,53.247) 1.238,49.316 ccw(c1.053,48.333) 0.053,48.333

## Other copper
Signal Layer 2 (GND):
  pour cut-out: 27.311,11.665 27.311,7.264 33.094,7.264 33.094,11.665
  pour cut-out: 27.27,19.271 27.27,14.87 33.053,14.87 33.053,19.271
Bottom Copper(SIG):
  region net GND: 11.303,75.362 11.182,75.241 11.182,67.729 18.92,67.729 18.92,75.349
  region net MOS_GND: 28.349,44.219 30.349,44.219 30.349,46.219 29.199,46.219 28.349,45.369
Multi-Layer:
  pour cut-out: 27.235,19.263 27.235,14.863 33.018,14.863 33.018,19.263
  pour cut-out: 27.311,11.665 27.311,7.264 33.094,7.264 33.094,11.665

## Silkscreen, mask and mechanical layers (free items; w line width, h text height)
Bottom Overlay:
  circle w0.254: c35.299,43.469 r0.813
  lines w0.254: 34.422,41.981 ccw(c33.199,41.369) 34.469,41.877
  text "+" at 36.588,42.659 h2.03 r135
Bottom Paste:
  circle w0.05: c45.822,69.952 r0.025
  circle w0.05: c45.972,70.102 r0.025
  circle w0.05: c45.822,70.102 r0.025
  circle w0.05: c45.972,69.952 r0.025
  circle w0.05: c45.822,70.352 r0.025
  circle w0.05: c45.972,70.502 r0.025
  circle w0.05: c45.822,70.502 r0.025
  circle w0.05: c45.972,70.352 r0.025
  circle w0.05: c45.972,70.752 r0.025
  circle w0.05: c45.822,70.902 r0.025
  circle w0.05: c45.972,70.902 r0.025
  circle w0.05: c45.822,70.752 r0.025
  circle w0.05: c45.422,69.952 r0.025
  circle w0.05: c45.572,70.102 r0.025
  circle w0.05: c45.422,70.102 r0.025
  circle w0.05: c45.572,69.952 r0.025
  circle w0.05: c45.422,70.352 r0.025
  circle w0.05: c45.572,70.502 r0.025
  circle w0.05: c45.422,70.502 r0.025
  circle w0.05: c45.572,70.352 r0.025
  circle w0.05: c45.572,70.752 r0.025
  circle w0.05: c45.422,70.902 r0.025
  circle w0.05: c45.572,70.902 r0.025
  circle w0.05: c45.422,70.752 r0.025
  region: 45.972,70.102 45.972,69.952 46.022,69.952 46.022,70.102
  rectangle: 45.822,70.102 45.972,70.152
  region: 45.822,69.952 45.822,70.102 45.772,70.102 45.772,69.952
  region: 45.972,69.952 45.822,69.952 45.822,69.902 45.972,69.902
  rectangle: 45.822,69.952 45.972,70.102
  region: 45.972,70.502 45.972,70.352 46.022,70.352 46.022,70.502
  rectangle: 45.822,70.502 45.972,70.552
  region: 45.822,70.352 45.822,70.502 45.772,70.502 45.772,70.352
  region: 45.972,70.352 45.822,70.352 45.822,70.302 45.972,70.302
  rectangle: 45.822,70.352 45.972,70.502
  rectangle: 45.822,70.752 45.972,70.902
  region: 45.972,70.752 45.822,70.752 45.822,70.702 45.972,70.702
  region: 45.822,70.752 45.822,70.902 45.772,70.902 45.772,70.752
  rectangle: 45.822,70.902 45.972,70.952
  region: 45.972,70.902 45.972,70.752 46.022,70.752 46.022,70.902
  region: 45.572,70.102 45.572,69.952 45.622,69.952 45.622,70.102
  rectangle: 45.422,70.102 45.572,70.152
  region: 45.422,69.952 45.422,70.102 45.372,70.102 45.372,69.952
  region: 45.572,69.952 45.422,69.952 45.422,69.902 45.572,69.902
  rectangle: 45.422,69.952 45.572,70.102
  region: 45.572,70.502 45.572,70.352 45.622,70.352 45.622,70.502
  rectangle: 45.422,70.502 45.572,70.552
  region: 45.422,70.352 45.422,70.502 45.372,70.502 45.372,70.352
  region: 45.572,70.352 45.422,70.352 45.422,70.302 45.572,70.302
  rectangle: 45.422,70.352 45.572,70.502
  rectangle: 45.422,70.752 45.572,70.902
  region: 45.572,70.752 45.422,70.752 45.422,70.702 45.572,70.702
  region: 45.422,70.752 45.422,70.902 45.372,70.902 45.372,70.752
  rectangle: 45.422,70.902 45.572,70.952
  region: 45.572,70.902 45.572,70.752 45.622,70.752 45.622,70.902
Board:
  circle w0.012: c41.227,13.779 r1.75
  circle w0.012: c19.239,13.664 r1.75
  circle w0.013: c19.228,13.658 r1.75
  circle w0.013: c41.227,13.808 r1.75
  lines w0.012: 33.632,86.716 cw(c33.6,86.678) 33.65,86.678 ; 33.824,89.987 ccw(c34.09,89.987) 33.827,89.946 ; 33.824,90.037 ccw(c34.091,90.037) 33.84,89.946 ; 34.049,90.931 cw(c34.234,90.447) 34.249,90.965 ; 34.049,91.196 cw(c34.249,91.046) 34.249,91.296 ; 34.05,90.994 cw(c34.237,90.665) 34.25,91.043 ; 34.05,91.196 cw(c34.25,91.046) 34.25,91.296 ; 34.056,90.931 ccw(c34.275,90.994) 34.494,90.931 ; 34.299,90.965 cw(c34.314,90.447) 34.499,90.931 ; 34.299,91.296 cw(c34.299,91.046) 34.499,91.196 ; 34.3,91.043 cw(c34.313,90.665) 34.5,90.994 ; 34.3,91.296 cw(c34.3,91.046) 34.5,91.196 ; 34.708,89.946 ccw(c34.457,90.037) 34.724,90.037 ; 34.721,89.946 ccw(c34.458,89.987) 34.724,89.987 ; 34.9,86.678 cw(c34.95,86.678) 34.919,86.716 ; 35.415,89.196 cw(c35.415,89.146) 35.465,89.146 ; 35.446,86.716 cw(c35.414,86.677) 35.464,86.677 ; 35.447,86.716 cw(c35.415,86.678) 35.465,86.678 ; 36.084,86.677 cw(c36.134,86.677) 36.102,86.716 ; 36.085,86.678 cw(c36.135,86.678) 36.104,86.716 ; 36.085,89.146 cw(c36.135,89.146) 36.135,89.196 ; 36.632,86.716 cw(c36.6,86.678) 36.65,86.678 ; 36.824,89.987 ccw(c37.09,89.987) 36.827,89.946 ; 36.824,90.037 ccw(c37.091,90.037) 36.84,89.946 ; 37.049,90.931 cw(c37.234,90.447) 37.249,90.965 ; 37.049,91.196 cw(c37.249,91.046) 37.249,91.296 ; 37.05,90.994 cw(c37.237,90.665) 37.25,91.043 ; 37.05,91.196 cw(c37.25,91.046) 37.25,91.296 ; 37.056,90.931 ccw(c37.275,90.994) 37.494,90.931 ; 37.299,90.965 cw(c37.314,90.447) 37.499,90.931 ; 37.299,91.296 cw(c37.299,91.046) 37.499,91.196 ; 37.3,91.043 cw(c37.313,90.665) 37.5,90.994 ; 37.3,91.296 cw(c37.3,91.046) 37.5,91.196 ; 37.708,89.946 ccw(c37.457,90.037) 37.724,90.037 ; 37.721,89.946 ccw(c37.458,89.987) 37.724,89.987 ; 37.9,86.678 cw(c37.95,86.678) 37.919,86.716 ; 38.415,89.196 cw(c38.415,89.146) 38.465,89.146 ; 38.446,86.716 cw(c38.414,86.677) 38.464,86.677 ; 38.447,86.716 cw(c38.415,86.678) 38.465,86.678 ; 39.084,86.677 cw(c39.134,86.677) 39.102,86.716 ; 39.085,86.678 cw(c39.135,86.678) 39.104,86.716 ; 39.085,89.146 cw(c39.135,89.146) 39.135,89.196 ; 39.632,86.716 cw(c39.6,86.678) 39.65,86.678 ; 39.824,89.987 ccw(c40.09,89.987) 39.827,89.946 ; 39.824,90.037 ccw(c40.091,90.037) 39.84,89.946 ; 40.049,90.931 cw(c40.234,90.447) 40.249,90.965 ; 40.049,91.196 cw(c40.249,91.046) 40.249,91.296 ; 40.05,90.994 cw(c40.237,90.665) 40.25,91.043 ; 40.05,91.196 cw(c40.25,91.046) 40.25,91.296 ; 40.056,90.931 ccw(c40.275,90.994) 40.494,90.931 ; 40.299,90.965 cw(c40.314,90.447) 40.499,90.931 ; 40.3,91.043 cw(c40.313,90.665) 40.5,90.994 ; 40.299,91.296 cw(c40.299,91.046) 40.499,91.196 ; 40.3,91.296 cw(c40.3,91.046) 40.5,91.196 ; 40.708,89.946 ccw(c40.457,90.037) 40.724,90.037 ; 40.721,89.946 ccw(c40.458,89.987) 40.724,89.987 ; 40.9,86.678 cw(c40.95,86.678) 40.919,86.716 ; 41.415,89.196 cw(c41.415,89.146) 41.465,89.146 ; 41.446,86.716 cw(c41.414,86.677) 41.464,86.677 ; 41.447,86.716 cw(c41.415,86.678) 41.465,86.678 ; 42.084,86.677 cw(c42.134,86.677) 42.102,86.716 ; 42.085,86.678 cw(c42.135,86.678) 42.104,86.716 ; 42.085,89.146 cw(c42.135,89.146) 42.135,89.196 ; 42.632,86.716 cw(c42.6,86.678) 42.65,86.678 ; 42.824,89.987 ccw(c43.09,89.987) 42.827,89.946 ; 42.824,90.037 ccw(c43.091,90.037) 42.84,89.946 ; 43.049,90.931 cw(c43.234,90.447) 43.249,90.965 ; 43.049,91.196 cw(c43.249,91.046) 43.249,91.296 ; 43.05,90.994 cw(c43.237,90.665) 43.25,91.043 ; 43.05,91.196 cw(c43.25,91.046) 43.25,91.296 ; 43.056,90.931 ccw(c43.275,90.994) 43.494,90.931 ; 43.299,90.965 cw(c43.314,90.447) 43.499,90.931 ; 43.299,91.296 cw(c43.299,91.046) 43.499,91.196 ; 43.3,91.043 cw(c43.313,90.665) 43.5,90.994 ; 43.3,91.296 cw(c43.3,91.046) 43.5,91.196 ; 43.708,89.946 ccw(c43.457,90.037) 43.724,90.037 ; 43.721,89.946 ccw(c43.458,89.987) 43.724,89.987 ; 43.9,86.678 cw(c43.95,86.678) 43.919,86.716 ; 44.415,89.196 cw(c44.415,89.146) 44.465,89.146 ; 44.446,86.716 cw(c44.414,86.677) 44.464,86.677 ; 44.447,86.716 cw(c44.415,86.678) 44.465,86.678 ; 45.084,86.677 cw(c45.134,86.677) 45.102,86.716 ; 45.085,86.678 cw(c45.135,86.678) 45.104,86.716 ; 45.085,89.146 cw(c45.135,89.146) 45.135,89.196 ; 45.632,86.716 cw(c45.6,86.678) 45.65,86.678 ; 45.824,89.987 ccw(c46.09,89.987) 45.827,89.946 ; 45.824,90.037 ccw(c46.091,90.037) 45.84,89.946 ; 46.049,90.931 cw(c46.234,90.447) 46.249,90.965 ; 46.049,91.196 cw(c46.249,91.046) 46.249,91.296 ; 46.05,90.994 cw(c46.237,90.665) 46.25,91.043 ; 46.05,91.196 cw(c46.25,91.046) 46.25,91.296 ; 46.056,90.931 ccw(c46.275,90.994) 46.494,90.931 ; 46.299,90.965 cw(c46.314,90.447) 46.499,90.931 ; 46.299,91.296 cw(c46.299,91.046) 46.499,91.196 ; 46.3,91.043 cw(c46.313,90.665) 46.5,90.994 ; 46.3,91.296 cw(c46.3,91.046) 46.5,91.196 ; 46.708,89.946 ccw(c46.457,90.037) 46.724,90.037 ; 46.721,89.946 ccw(c46.458,89.987) 46.724,89.987 ; 46.9,86.678 cw(c46.95,86.678) 46.919,86.716 ; 34.049,90.864 cw(c34.234,90.38) 34.249,90.898 ccw(c34.274,90.899) 34.299,90.898 cw(c34.314,90.38) 34.499,90.864 cw(c34.274,90.874) 34.049,90.864 ; 37.049,90.864 cw(c37.234,90.38) 37.249,90.898 ccw(c37.274,90.899) 37.299,90.898 cw(c37.314,90.38) 37.499,90.864 cw(c37.274,90.874) 37.049,90.864 ; 40.049,90.864 cw(c40.234,90.38) 40.249,90.898 ccw(c40.274,90.899) 40.299,90.898 cw(c40.314,90.38) 40.499,90.864 cw(c40.274,90.874) 40.049,90.864 ; 43.049,90.864 cw(c43.234,90.38) 43.249,90.898 ccw(c43.274,90.899) 43.299,90.898 cw(c43.314,90.38) 43.499,90.864 cw(c43.274,90.874) 43.049,90.864 ; 46.049,90.864 cw(c46.234,90.38) 46.249,90.898 ccw(c46.274,90.899) 46.299,90.898 cw(c46.314,90.38) 46.499,90.864 cw(c46.274,90.874) 46.049,90.864
  lines w0.013: 0.053,7.862 ccw(c1.053,7.862) 1.438,6.939 cw(c2.977,3.247) 6.482,1.319 ccw(c7.358,0.838) 7.358,-0.162 ; 0.053,48.333 cw(c1.053,48.333) 1.238,49.316 ccw(c1.977,53.247) 1.238,57.178 cw(c1.053,58.161) 0.053,58.161 ; 0.053,83.322 cw(c1.053,83.322) 1.438,84.245 ccw(c2.977,87.937) 6.663,89.49 cw(c7.584,89.879) 7.3,90.838 ; 6.553,61.242 ccw(c6.553,62.242) 7.553,62.242 ; 6.553,80.142 cw(c6.553,79.142) 7.553,79.142 ; 53.225,-0.162 ccw(c53.225,0.838) 54.102,1.319 cw(c57.607,3.247) 56.007,6.913 ; 53.308,90.838 cw(c53.002,89.885) 53.923,89.496 ccw(c57.607,87.937) 59.146,84.245 cw(c59.53,83.322) 60.53,83.322 ; 56.73,59.192 ccw(c57.73,59.192) 57.73,58.192 ; 56.73,74.192 cw(c57.73,74.192) 57.73,75.192 ; 60.53,43.083 ccw(c59.53,43.083) 59.346,44.066 ; 60.53,52.911 cw(c59.53,52.911) 59.346,51.928 ; 59.346,44.066 cw(c58.607,47.997) 59.346,51.928 ; 59.346,44.066 cw(c58.607,47.997) 59.346,51.928
Top 3D Body:
  circle w0.06: c45.897,70.827 r0.08
Bottom Assembly:
  text ".Designator" at 54.247,51.036 h1
Bottom Courtyard:
  region: 35.387,44.149 35.387,42.749 35.187,42.749 35.187,44.149
  region: 35.987,43.349 34.587,43.349 34.587,43.549 35.987,43.549
  region: 36.014,45.986 35.574,45.986 35.574,43.586 36.034,43.586
  region: 36.951,44.586 36.951,45.026 34.551,45.026 34.551,44.566
  region: 30.854,42.506 30.854,40.566 29.874,41.546
  region: 34.387,43.449 34.487,43.449 34.491,43.528 34.521,43.681 34.581,43.826 34.668,43.957 34.779,44.068 34.91,44.155 35.055,44.215 35.208,44.245 35.287,44.249 35.287,44.349 35.198,44.349 35.024,44.315 34.861,44.247 34.713,44.148 34.588,44.023 34.489,43.875 34.421,43.712 34.387,43.538 34.387,43.449
  region: 35.287,44.349 35.287,44.249 35.365,44.245 35.519,44.215 35.664,44.155 35.794,44.068 35.905,43.957 35.992,43.826 36.052,43.681 36.083,43.528 36.087,43.449 36.187,43.449 36.187,43.538 36.152,43.712 36.084,43.875 35.986,44.023 35.861,44.148 35.713,44.247 35.549,44.315 35.376,44.349 35.287,44.349
  region: 36.187,43.449 36.087,43.449 36.083,43.371 36.052,43.217 35.992,43.072 35.905,42.942 35.794,42.831 35.664,42.744 35.519,42.684 35.365,42.653 35.287,42.649 35.287,42.549 35.376,42.549 35.549,42.584 35.713,42.652 35.861,42.75 35.986,42.875 36.084,43.023 36.152,43.187 36.187,43.36 36.187,43.449
  region: 35.287,42.549 35.287,42.649 35.208,42.653 35.055,42.684 34.91,42.744 34.779,42.831 34.668,42.942 34.581,43.072 34.521,43.217 34.491,43.371 34.487,43.449 34.387,43.449 34.387,43.36 34.421,43.187 34.489,43.023 34.588,42.875 34.713,42.75 34.861,42.652 35.024,42.584 35.198,42.549 35.287,42.549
